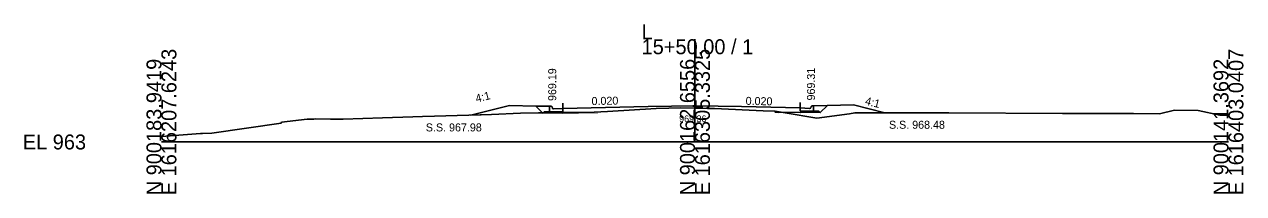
# Model space of a CAD drawing. Extents: x 1009 to 7438, y -1586 to 7964.
# Drawn here: x 1009.2 to 1237.7, y 3414 to 3445.8 of the extents above; entities that cross this region are included whole.
import ezdxf

# ---------------------------------------------------------------- set-up
doc = ezdxf.new("R2010")
doc.units = 0
for name, color, linetype in [('Exist Cross Section Cell', 7, 'Continuous'), ('Exist XS Center Line Elevation Label', 7, 'Continuous'), ('Exist XS Ground Line', 7, 'Continuous'), ('Prop XS Dump Level', 7, 'Continuous'), ('Prop XS Earthwork Shape', 7, 'Continuous'), ('Prop XS EOT Tick Mark', 7, 'Continuous'), ('Prop XS Finish Grade', 7, 'Continuous'), ('Prop XS Finish Grade CurbGutter', 7, 'Continuous'), ('Prop XS Finish Grade Earthwork', 7, 'Continuous'), ('Prop XS Finish Grade Pavement', 7, 'Continuous'), ('Prop XS Hydro Elevations', 7, 'Continuous'), ('Prop XS Pvmt Edge Slope', 7, 'Continuous'), ('Prop XS SE Text', 7, 'Continuous'), ('Prop XS Side Slope Text', 7, 'Continuous'), ('Prop XS SS Elevation Text', 7, 'Continuous'), ('Prop XS Subgrade CurbGutter', 7, 'Continuous'), ('Prop XS Subgrade Earthwork', 7, 'Continuous')]:
    doc.layers.add(name, color=color, linetype=linetype)

msp = doc.modelspace()

# ---------------------------------------------------------------- linework, layer by layer
at = {"layer": 'Exist Cross Section Cell'}
for p, q in [((1134.89, 3423.73), (1134.89, 3443)), ((1034.89, 3423.73), (1134.89, 3423.73)), ((1134.89, 3423.73), (1234.89, 3423.73))]:
    msp.add_line(p, q, dxfattribs=at)
at = {"layer": 'Exist XS Ground Line'}
for p, q in [((1057.38, 3427.46), (1062.23, 3428.02)), ((1062.23, 3428.02), (1063.45, 3428.04)), ((1063.45, 3428.04), (1063.8, 3428.07)), ((1063.8, 3428.07), (1066.57, 3428.03)), ((1066.57, 3428.03), (1068.96, 3428.04)), ((1068.96, 3428.04), (1076.32, 3428.29)), ((1076.32, 3428.29), (1082.01, 3428.47)), ((1082.01, 3428.47), (1083.81, 3428.54)), ((1083.81, 3428.54), (1086.06, 3428.6)), ((1086.06, 3428.6), (1096.77, 3428.86)), ((1096.77, 3428.86), (1102.21, 3429.12)), ((1102.21, 3429.12), (1108.97, 3429.25)), ((1108.97, 3429.25), (1116.01, 3429.3)), ((1116.01, 3429.3), (1118.52, 3429.45)), ((1118.52, 3429.45), (1127.62, 3430)), ((1127.62, 3430), (1130.02, 3430.08)), ((1130.02, 3430.08), (1132.25, 3430.15)), ((1132.25, 3430.15), (1134.89, 3430.09)), ((1134.89, 3430.09), (1137.25, 3430.03)), ((1137.25, 3430.03), (1138.55, 3430.01)), ((1138.55, 3430.01), (1147.66, 3429.58)), ((1147.66, 3429.58), (1149.91, 3429.48)), ((1149.91, 3429.48), (1151.78, 3429.18)), ((1151.78, 3429.18), (1157.76, 3428.17)), ((1157.76, 3428.17), (1163.83, 3429.04)), ((1163.83, 3429.04), (1164.83, 3429.18)), ((1164.83, 3429.18), (1168.71, 3429.22)), ((1168.71, 3429.22), (1182.49, 3429.21)), ((1182.49, 3429.21), (1203.77, 3429.09)), ((1203.77, 3429.09), (1207.49, 3429.1)), ((1207.49, 3429.1), (1208.34, 3429.08)), ((1208.34, 3429.08), (1210.89, 3429.06)), ((1210.89, 3429.06), (1217.08, 3429.05)), ((1217.08, 3429.05), (1221.94, 3428.98)), ((1221.94, 3428.98), (1224.79, 3429.7)), ((1224.79, 3429.7), (1229.23, 3429.61)), ((1229.23, 3429.61), (1233.25, 3428.78)), ((1233.25, 3428.78), (1234.89, 3428.75)), ((1044.31, 3425.36), (1057.33, 3427.25)), ((1057.33, 3427.25), (1057.38, 3427.46)), ((1034.89, 3424.77), (1042.18, 3425.31)), ((1042.18, 3425.31), (1042.61, 3425.35)), ((1042.61, 3425.35), (1044.31, 3425.36))]:
    msp.add_line(p, q, dxfattribs=at)
at = {"layer": 'Prop XS Dump Level'}
for p, q in [((1126.14, 3430.36), (1110.14, 3430.04)), ((1110.14, 3430.04), (1126.14, 3430.36)), ((1134.89, 3430.54), (1126.14, 3430.36)), ((1126.14, 3430.36), (1134.89, 3430.54)), ((1143.64, 3430.36), (1134.89, 3430.54)), ((1134.89, 3430.54), (1143.64, 3430.36))]:
    msp.add_line(p, q, dxfattribs=at)
at = {"layer": 'Prop XS Earthwork Shape'}
for points in [[(1092.88, 3428.77), (1096.77, 3428.86), (1102.21, 3429.12), (1106.33, 3429.2), (1105.05, 3430.48), (1100.14, 3430.58)], [(1157.76, 3428.17), (1163.83, 3429.04), (1164.83, 3429.18), (1168.71, 3429.22), (1170.49, 3429.22), (1164.64, 3430.68), (1159.73, 3430.58), (1158.39, 3429.24), (1154.64, 3429.31), (1154.64, 3429.23), (1151.03, 3429.3), (1151.78, 3429.18)], [(1106.39, 3429.14), (1106.33, 3429.2), (1106.45, 3429.2)], [(1106.45, 3429.2), (1106.39, 3429.14), (1110.14, 3429.21), (1110.14, 3429.13), (1115.98, 3429.24), (1115.98, 3429.3), (1108.97, 3429.25)], [(1149.94, 3429.48), (1151.03, 3429.3), (1149.94, 3429.32)]]:
    msp.add_lwpolyline(points, close=True, dxfattribs=at)
at = {"layer": 'Prop XS EOT Tick Mark'}
for p, q in [((1110.14, 3430.04), (1110.14, 3431.04)), ((1154.64, 3430.14), (1154.64, 3431.14))]:
    msp.add_line(p, q, dxfattribs=at)
at = {"layer": 'Prop XS Finish Grade'}
for p, q in [((1107.64, 3430.42), (1105.05, 3430.48)), ((1157.14, 3430.52), (1159.73, 3430.58))]:
    msp.add_line(p, q, dxfattribs=at)
at = {"layer": 'Prop XS Finish Grade CurbGutter'}
for p, q in [((1107.64, 3430.42), (1107.89, 3430.42)), ((1107.89, 3430.42), (1108.02, 3430.4)), ((1108.11, 3430.3), (1108.02, 3430.4)), ((1108.18, 3430.05), (1108.11, 3430.3)), ((1156.61, 3430.15), (1156.67, 3430.4)), ((1156.67, 3430.4), (1156.77, 3430.5)), ((1156.89, 3430.52), (1156.77, 3430.5)), ((1157.14, 3430.52), (1156.89, 3430.52)), ((1108.27, 3429.96), (1108.18, 3430.05)), ((1108.39, 3429.94), (1108.27, 3429.96)), ((1110.14, 3430.04), (1108.39, 3429.94)), ((1154.64, 3430.14), (1156.39, 3430.04)), ((1156.39, 3430.04), (1156.52, 3430.06)), ((1156.52, 3430.06), (1156.61, 3430.15))]:
    msp.add_line(p, q, dxfattribs=at)
at = {"layer": 'Prop XS Finish Grade Earthwork'}
for p, q in [((1100.14, 3430.58), (1092.88, 3428.77)), ((1105.05, 3430.48), (1100.14, 3430.58)), ((1159.73, 3430.58), (1164.64, 3430.68)), ((1164.64, 3430.68), (1170.49, 3429.22))]:
    msp.add_line(p, q, dxfattribs=at)
at = {"layer": 'Prop XS Finish Grade Pavement'}
for p, q in [((1110.14, 3430.04), (1126.14, 3430.36)), ((1126.14, 3430.36), (1134.89, 3430.54)), ((1134.89, 3430.54), (1143.64, 3430.36)), ((1143.64, 3430.36), (1154.64, 3430.14))]:
    msp.add_line(p, q, dxfattribs=at)
at = {"layer": 'Prop XS Pvmt Edge Slope'}
for p, q in [((1106.64, 3429.39), (1106.39, 3429.14)), ((1107.64, 3429.41), (1106.64, 3429.39)), ((1157.14, 3429.51), (1158.14, 3429.49)), ((1158.14, 3429.49), (1158.39, 3429.24))]:
    msp.add_line(p, q, dxfattribs=at)
at = {"layer": 'Prop XS Subgrade CurbGutter'}
for p, q in [((1107.64, 3429.41), (1107.64, 3430.42)), ((1157.14, 3429.51), (1157.14, 3430.52)), ((1110.14, 3429.46), (1107.64, 3429.41)), ((1110.14, 3430.04), (1110.14, 3429.46)), ((1154.64, 3430.14), (1154.64, 3429.56)), ((1154.64, 3429.56), (1157.14, 3429.51))]:
    msp.add_line(p, q, dxfattribs=at)
at = {"layer": 'Prop XS Subgrade Earthwork'}
for p, q in [((1106.39, 3429.14), (1105.05, 3430.48)), ((1158.39, 3429.24), (1159.73, 3430.58)), ((1110.14, 3429.21), (1106.39, 3429.14)), ((1115.98, 3429.24), (1110.14, 3429.13)), ((1110.14, 3429.13), (1110.14, 3429.21)), ((1115.98, 3429.24), (1115.98, 3429.3)), ((1149.94, 3429.32), (1149.94, 3429.48)), ((1149.94, 3429.32), (1154.64, 3429.23)), ((1154.64, 3429.31), (1158.39, 3429.24)), ((1154.64, 3429.23), (1154.64, 3429.31))]:
    msp.add_line(p, q, dxfattribs=at)

# ---------------------------------------------------------------- texts
at = {"layer": 'Exist Cross Section Cell'}
for s, p in [('L', (1124.89, 3443)), ('15+50.00 / 1', (1124.89, 3440.2)), ('EL 963', (1008.89, 3422.33))]:
    msp.add_text(s, height=2.8, dxfattribs=at).set_placement(p)
for s, p in [('E 1616207.6243', (1037.69, 3413.73)), ('E 1616305.3325', (1137.69, 3413.73)), ('E 1616403.0407', (1237.69, 3413.73)), ('N 900183.9419', (1034.89, 3413.73)), ('N 900162.6556', (1134.89, 3413.73)), ('N 900141.3692', (1234.89, 3413.73))]:
    msp.add_text(s, height=2.8, rotation=90, dxfattribs=at).set_placement(p)
at = {"layer": 'Exist XS Center Line Elevation Label'}
msp.add_text('969.36', height=1.25, dxfattribs=at).set_placement((1131.93, 3427.46))
at = {"layer": 'Prop XS Dump Level'}
for p in [(1115.98, 3429), (1149.94, 3429.18)]:
    msp.add_text('Eop', height=0.3, dxfattribs=at).set_placement(p)
at = {"layer": 'Prop XS Hydro Elevations'}
for s, p in [('969.19', (1108.89, 3431.42)), ('969.31', (1157.39, 3431.52))]:
    msp.add_text(s, height=1.5, rotation=90, dxfattribs=at).set_placement(p)
at = {"layer": 'Prop XS SE Text'}
for rotation, p in [(1.1458, (1115.52, 3430.65)), (358.8542, (1144.38, 3430.7))]:
    msp.add_text('0.020', height=1.5, rotation=rotation, dxfattribs=at).set_placement(p)
at = {"layer": 'Prop XS Side Slope Text'}
for rotation, p in [(14.0362, (1093.95, 3431.12)), (345.9638, (1166.67, 3430.77))]:
    msp.add_text('4:1', height=1.5, rotation=rotation, dxfattribs=at).set_placement(p)
at = {"layer": 'Prop XS SS Elevation Text'}
for s, p in [('S.S. 967.98', (1084.45, 3425.71)), ('S.S. 968.48', (1171.26, 3426.21))]:
    msp.add_text(s, height=1.5, dxfattribs=at).set_placement(p)

doc.saveas('drawing.dxf')
